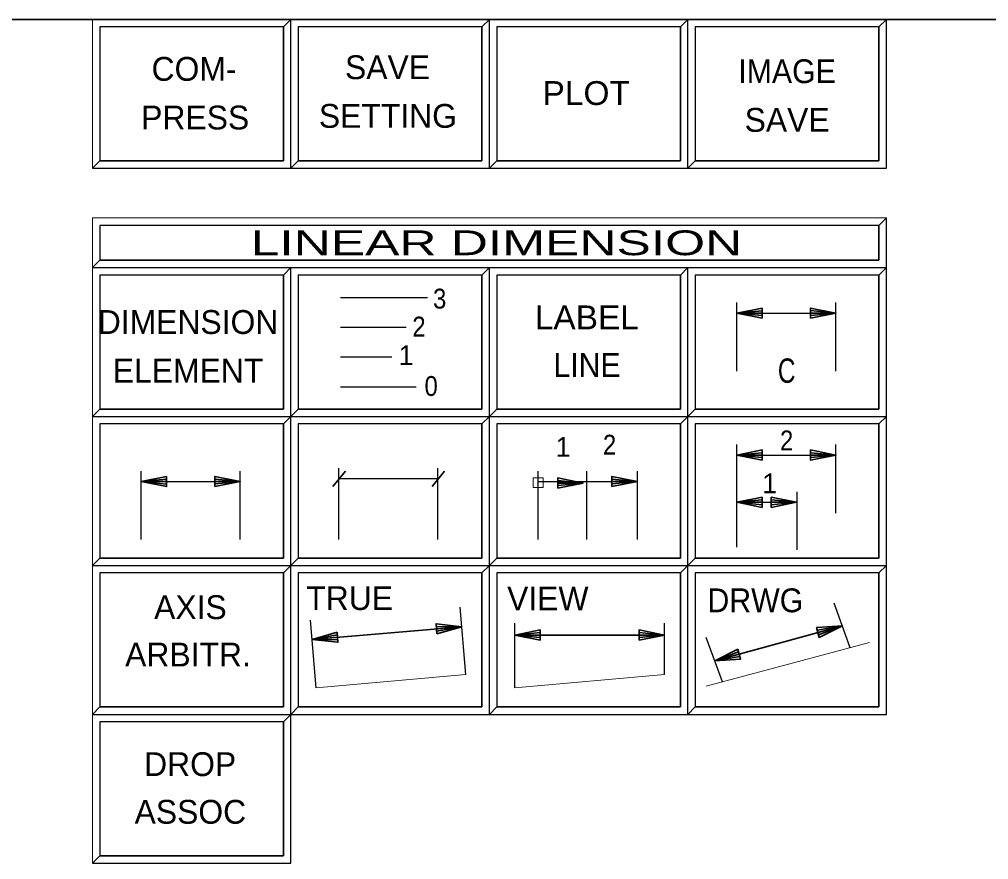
# Model space of a CAD drawing. Extents: x 95906.8 to 95923.6, y 90964.8 to 90972.8.
# Drawn here: x 95908.785 to 95910.738, y 90971.069 to 90972.762 of the extents above; entities that cross this region are included whole.
import ezdxf
from ezdxf.enums import TextEntityAlignment as Align

# ---------------------------------------------------------------- set-up
doc = ezdxf.new("R2010")
doc.units = 0
doc.header["$LTSCALE"] = 0.019
for name, color, linetype, lineweight in [('11', 7, 'Continuous', 25), ('12', 7, 'Continuous', 25), ('17', 7, 'Continuous', 25), ('2', 7, 'Continuous', 13), ('3', 7, 'Continuous', 25), ('6', 7, 'Continuous', 25), ('7', 7, 'Continuous', 35)]:
    doc.layers.add(name, color=color, linetype=linetype, lineweight=lineweight)

msp = doc.modelspace()

# ---------------------------------------------------------------- linework, layer by layer
at = {"layer": '11'}
for points in [[(95908.9473, 90972.4767), (95909.3173, 90972.4767), (95909.3173, 90972.7467), (95908.9473, 90972.7467)], [(95909.3473, 90972.4767), (95909.7173, 90972.4767), (95909.7173, 90972.7467), (95909.3473, 90972.7467)], [(95909.7473, 90972.4767), (95910.1173, 90972.4767), (95910.1173, 90972.7467), (95909.7473, 90972.7467)], [(95908.9473, 90971.9767), (95909.3173, 90971.9767), (95909.3173, 90972.2467), (95908.9473, 90972.2467)], [(95909.3473, 90971.9767), (95909.7173, 90971.9767), (95909.7173, 90972.2467), (95909.3473, 90972.2467)], [(95909.7473, 90971.9767), (95910.1173, 90971.9767), (95910.1173, 90972.2467), (95909.7473, 90972.2467)], [(95910.1473, 90971.9767), (95910.5173, 90971.9767), (95910.5173, 90972.2467), (95910.1473, 90972.2467)], [(95909.3473, 90971.6767), (95909.7173, 90971.6767), (95909.7173, 90971.9467), (95909.3473, 90971.9467)], [(95909.7473, 90971.6767), (95910.1173, 90971.6767), (95910.1173, 90971.9467), (95909.7473, 90971.9467)], [(95910.1473, 90971.6767), (95910.5173, 90971.6767), (95910.5173, 90971.9467), (95910.1473, 90971.9467)], [(95908.9473, 90971.3767), (95909.3173, 90971.3767), (95909.3173, 90971.6467), (95908.9473, 90971.6467)], [(95909.3473, 90971.3767), (95909.7173, 90971.3767), (95909.7173, 90971.6467), (95909.3473, 90971.6467)], [(95909.7473, 90971.3767), (95910.1173, 90971.3767), (95910.1173, 90971.6467), (95909.7473, 90971.6467)], [(95910.1473, 90971.3767), (95910.5173, 90971.3767), (95910.5173, 90971.6467), (95910.1473, 90971.6467)], [(95908.9473, 90971.0767), (95909.3173, 90971.0767), (95909.3173, 90971.3467), (95908.9473, 90971.3467)]]:
    msp.add_lwpolyline(points, close=True, dxfattribs=at)
at = {"layer": '12'}
for points in [[(95910.1473, 90972.4767), (95910.5173, 90972.4767), (95910.5173, 90972.7467), (95910.1473, 90972.7467)], [(95908.9473, 90971.6767), (95909.3173, 90971.6767), (95909.3173, 90971.9467), (95908.9473, 90971.9467)]]:
    msp.add_lwpolyline(points, close=True, dxfattribs=at)
at = {"layer": '17'}
msp.add_lwpolyline([(95908.9473, 90972.2767), (95910.5173, 90972.2767), (95910.5173, 90972.3467), (95908.9473, 90972.3467)], close=True, dxfattribs=at)
at = {"layer": '2'}
for points in [[(95908.9323, 90972.7617), (95908.9323, 90972.4617), (95908.9473, 90972.4767), (95908.9473, 90972.7467), (95909.3173, 90972.7467), (95909.3323, 90972.7617)], [(95909.3323, 90972.7617), (95909.3323, 90972.4617), (95909.3473, 90972.4767), (95909.3473, 90972.7467), (95909.7173, 90972.7467), (95909.7323, 90972.7617)], [(95909.7323, 90972.7617), (95909.7323, 90972.4617), (95909.7473, 90972.4767), (95909.7473, 90972.7467), (95910.1173, 90972.7467), (95910.1323, 90972.7617)], [(95910.1323, 90972.7617), (95910.1323, 90972.4617), (95910.1473, 90972.4767), (95910.1473, 90972.7467), (95910.5173, 90972.7467), (95910.5323, 90972.7617)], [(95908.9323, 90972.3617), (95908.9323, 90972.2617), (95908.9473, 90972.2767), (95908.9473, 90972.3467), (95910.5173, 90972.3467), (95910.5323, 90972.3617)], [(95908.9323, 90972.2617), (95908.9323, 90971.9617), (95908.9473, 90971.9767), (95908.9473, 90972.2467), (95909.3173, 90972.2467), (95909.3323, 90972.2617)], [(95909.3323, 90972.2617), (95909.3323, 90971.9617), (95909.3473, 90971.9767), (95909.3473, 90972.2467), (95909.7173, 90972.2467), (95909.7323, 90972.2617)], [(95909.7323, 90972.2617), (95909.7323, 90971.9617), (95909.7473, 90971.9767), (95909.7473, 90972.2467), (95910.1173, 90972.2467), (95910.1323, 90972.2617)], [(95910.1323, 90972.2617), (95910.1323, 90971.9617), (95910.1473, 90971.9767), (95910.1473, 90972.2467), (95910.5173, 90972.2467), (95910.5323, 90972.2617)], [(95908.9323, 90971.9617), (95908.9323, 90971.6617), (95908.9473, 90971.6767), (95908.9473, 90971.9467), (95909.3173, 90971.9467), (95909.3323, 90971.9617)], [(95909.3323, 90971.9617), (95909.3323, 90971.6617), (95909.3473, 90971.6767), (95909.3473, 90971.9467), (95909.7173, 90971.9467), (95909.7323, 90971.9617)], [(95909.7323, 90971.9617), (95909.7323, 90971.6617), (95909.7473, 90971.6767), (95909.7473, 90971.9467), (95910.1173, 90971.9467), (95910.1323, 90971.9617)], [(95910.1323, 90971.9617), (95910.1323, 90971.6617), (95910.1473, 90971.6767), (95910.1473, 90971.9467), (95910.5173, 90971.9467), (95910.5323, 90971.9617)], [(95908.9323, 90971.6617), (95908.9323, 90971.3617), (95908.9473, 90971.3767), (95908.9473, 90971.6467), (95909.3173, 90971.6467), (95909.3323, 90971.6617)], [(95909.3323, 90971.6617), (95909.3323, 90971.3617), (95909.3473, 90971.3767), (95909.3473, 90971.6467), (95909.7173, 90971.6467), (95909.7323, 90971.6617)], [(95909.7323, 90971.6617), (95909.7323, 90971.3617), (95909.7473, 90971.3767), (95909.7473, 90971.6467), (95910.1173, 90971.6467), (95910.1323, 90971.6617)], [(95910.1323, 90971.6617), (95910.1323, 90971.3617), (95910.1473, 90971.3767), (95910.1473, 90971.6467), (95910.5173, 90971.6467), (95910.5323, 90971.6617)], [(95908.9323, 90971.3617), (95908.9323, 90971.0617), (95908.9473, 90971.0767), (95908.9473, 90971.3467), (95909.3173, 90971.3467), (95909.3323, 90971.3617)]]:
    msp.add_lwpolyline(points, close=True, dxfattribs=at)
at = {"layer": '3'}
for points in [[(95908.9323, 90972.4617), (95909.3323, 90972.4617), (95909.3323, 90972.7617), (95909.3173, 90972.7467), (95909.3173, 90972.4767), (95908.9473, 90972.4767)], [(95909.3323, 90972.4617), (95909.7323, 90972.4617), (95909.7323, 90972.7617), (95909.7173, 90972.7467), (95909.7173, 90972.4767), (95909.3473, 90972.4767)], [(95909.7323, 90972.4617), (95910.1323, 90972.4617), (95910.1323, 90972.7617), (95910.1173, 90972.7467), (95910.1173, 90972.4767), (95909.7473, 90972.4767)], [(95910.1323, 90972.4617), (95910.5323, 90972.4617), (95910.5323, 90972.7617), (95910.5173, 90972.7467), (95910.5173, 90972.4767), (95910.1473, 90972.4767)], [(95908.9323, 90972.2617), (95910.5323, 90972.2617), (95910.5323, 90972.3617), (95910.5173, 90972.3467), (95910.5173, 90972.2767), (95908.9473, 90972.2767)], [(95908.9323, 90971.9617), (95909.3323, 90971.9617), (95909.3323, 90972.2617), (95909.3173, 90972.2467), (95909.3173, 90971.9767), (95908.9473, 90971.9767)], [(95909.3323, 90971.9617), (95909.7323, 90971.9617), (95909.7323, 90972.2617), (95909.7173, 90972.2467), (95909.7173, 90971.9767), (95909.3473, 90971.9767)], [(95909.7323, 90971.9617), (95910.1323, 90971.9617), (95910.1323, 90972.2617), (95910.1173, 90972.2467), (95910.1173, 90971.9767), (95909.7473, 90971.9767)], [(95910.1323, 90971.9617), (95910.5323, 90971.9617), (95910.5323, 90972.2617), (95910.5173, 90972.2467), (95910.5173, 90971.9767), (95910.1473, 90971.9767)], [(95908.9323, 90971.6617), (95909.3323, 90971.6617), (95909.3323, 90971.9617), (95909.3173, 90971.9467), (95909.3173, 90971.6767), (95908.9473, 90971.6767)], [(95909.3323, 90971.6617), (95909.7323, 90971.6617), (95909.7323, 90971.9617), (95909.7173, 90971.9467), (95909.7173, 90971.6767), (95909.3473, 90971.6767)], [(95909.7323, 90971.6617), (95910.1323, 90971.6617), (95910.1323, 90971.9617), (95910.1173, 90971.9467), (95910.1173, 90971.6767), (95909.7473, 90971.6767)], [(95910.1323, 90971.6617), (95910.5323, 90971.6617), (95910.5323, 90971.9617), (95910.5173, 90971.9467), (95910.5173, 90971.6767), (95910.1473, 90971.6767)], [(95908.9323, 90971.3617), (95909.3323, 90971.3617), (95909.3323, 90971.6617), (95909.3173, 90971.6467), (95909.3173, 90971.3767), (95908.9473, 90971.3767)], [(95909.3323, 90971.3617), (95909.7323, 90971.3617), (95909.7323, 90971.6617), (95909.7173, 90971.6467), (95909.7173, 90971.3767), (95909.3473, 90971.3767)], [(95909.7323, 90971.3617), (95910.1323, 90971.3617), (95910.1323, 90971.6617), (95910.1173, 90971.6467), (95910.1173, 90971.3767), (95909.7473, 90971.3767)], [(95910.1323, 90971.3617), (95910.5323, 90971.3617), (95910.5323, 90971.6617), (95910.5173, 90971.6467), (95910.5173, 90971.3767), (95910.1473, 90971.3767)], [(95908.9323, 90971.0617), (95909.3323, 90971.0617), (95909.3323, 90971.3617), (95909.3173, 90971.3467), (95909.3173, 90971.0767), (95908.9473, 90971.0767)]]:
    msp.add_lwpolyline(points, close=True, dxfattribs=at)
at = {"layer": '6'}
for p, q in [((95909.4323, 90972.2017), (95909.6076, 90972.2017)), ((95910.2307, 90972.0533), (95910.2307, 90972.1912)), ((95910.4305, 90972.0533), (95910.4305, 90972.1912)), ((95910.2307, 90972.1701), (95910.4305, 90972.1701)), ((95909.4323, 90972.1417), (95909.5646, 90972.1417)), ((95909.4323, 90972.0817), (95909.5356, 90972.0817)), ((95909.4323, 90972.0217), (95909.5847, 90972.0217)), ((95910.2307, 90971.6987), (95910.2307, 90971.9052)), ((95910.4305, 90971.7673), (95910.4305, 90971.9052)), ((95910.2307, 90971.8841), (95910.4305, 90971.8841)), ((95909.4289, 90971.714), (95909.4289, 90971.858)), ((95909.6287, 90971.714), (95909.6287, 90971.858)), ((95909.0307, 90971.714), (95909.0307, 90971.8519)), ((95909.2305, 90971.714), (95909.2305, 90971.8519)), ((95909.4289, 90971.8369), (95909.6287, 90971.8369)), ((95909.8307, 90971.714), (95909.8307, 90971.8519)), ((95909.929, 90971.714), (95909.929, 90971.8519)), ((95910.0305, 90971.714), (95910.0305, 90971.8519)), ((95909.0307, 90971.8308), (95909.2305, 90971.8308)), ((95909.8307, 90971.8308), (95910.0305, 90971.8308)), ((95910.3526, 90971.6929), (95910.3526, 90971.81)), ((95910.2307, 90971.7889), (95910.3515, 90971.7889)), ((95910.4596, 90971.4961), (95910.427, 90971.5856)), ((95909.6851, 90971.4419), (95909.6732, 90971.5776)), ((95909.3835, 90971.4155), (95909.3716, 90971.5512)), ((95909.7835, 90971.4155), (95909.7835, 90971.5454)), ((95910.0851, 90971.4419), (95910.0851, 90971.5454)), ((95910.2019, 90971.427), (95910.1693, 90971.5165))]:
    msp.add_line(p, q, dxfattribs=at)
at = {"layer": '6', "lineweight": 35}
for p, q in [((95910.2307, 90972.1701), (95910.2819, 90972.1749)), ((95910.2819, 90972.1701), (95910.2307, 90972.1701)), ((95910.3793, 90972.1701), (95910.4305, 90972.1701)), ((95910.4305, 90972.1701), (95910.3793, 90972.1653)), ((95910.2307, 90971.8841), (95910.2819, 90971.8889)), ((95910.2307, 90971.8841), (95910.2819, 90971.8889)), ((95910.2819, 90971.8841), (95910.2307, 90971.8841)), ((95910.2819, 90971.8841), (95910.2307, 90971.8841)), ((95910.4305, 90971.8841), (95910.3793, 90971.8889)), ((95910.4305, 90971.8841), (95910.3793, 90971.8889)), ((95910.3793, 90971.8841), (95910.4305, 90971.8841)), ((95910.3793, 90971.8841), (95910.4305, 90971.8841)), ((95909.0307, 90971.8308), (95909.0819, 90971.8356)), ((95909.417, 90971.821), (95909.4423, 90971.8518)), ((95909.6169, 90971.821), (95909.6422, 90971.8518)), ((95909.0819, 90971.8308), (95909.0307, 90971.8308)), ((95909.1793, 90971.8308), (95909.2305, 90971.8308)), ((95909.2305, 90971.8308), (95909.1793, 90971.826)), ((95909.87, 90971.8278), (95909.9212, 90971.8278)), ((95909.9212, 90971.8278), (95909.87, 90971.823)), ((95909.9793, 90971.8308), (95910.0305, 90971.8308)), ((95910.0305, 90971.8308), (95909.9793, 90971.826)), ((95910.2307, 90971.7889), (95910.2819, 90971.7937)), ((95910.2819, 90971.7889), (95910.2307, 90971.7889)), ((95910.3003, 90971.7889), (95910.3515, 90971.7889)), ((95910.3515, 90971.7889), (95910.3003, 90971.7841)), ((95909.3751, 90971.5129), (95909.6767, 90971.5384)), ((95909.3751, 90971.5129), (95909.4257, 90971.522)), ((95909.6257, 90971.5341), (95909.6767, 90971.5384)), ((95909.6767, 90971.5384), (95909.6261, 90971.5293)), ((95909.7835, 90971.5216), (95909.8347, 90971.5264)), ((95909.7835, 90971.5216), (95910.0851, 90971.5216)), ((95909.8347, 90971.5216), (95909.7835, 90971.5216)), ((95910.0339, 90971.5216), (95910.0851, 90971.5216)), ((95910.0851, 90971.5216), (95910.0339, 90971.5168)), ((95910.1865, 90971.4695), (95910.4436, 90971.5403)), ((95910.3942, 90971.5267), (95910.4436, 90971.5403)), ((95910.4436, 90971.5403), (95910.3955, 90971.5221)), ((95909.4261, 90971.5172), (95909.3751, 90971.5129)), ((95910.1865, 90971.4695), (95910.2346, 90971.4877)), ((95910.2359, 90971.4831), (95910.1865, 90971.4695))]:
    msp.add_line(p, q, dxfattribs=at)
at = {"layer": '6', "lineweight": 13}
for p, q in [((95910.1695, 90971.4183), (95910.4981, 90971.5064)), ((95909.3835, 90971.4155), (95909.6851, 90971.4419)), ((95909.7835, 90971.4155), (95910.0851, 90971.4419))]:
    msp.add_line(p, q, dxfattribs=at)
at = {"layer": '6', "lineweight": 35}
for points in [[(95910.2819, 90972.1803), (95910.2819, 90972.1599), (95910.2307, 90972.1701)], [(95910.2819, 90972.1803), (95910.2307, 90972.1701), (95910.2819, 90972.1651)], [(95910.3793, 90972.1599), (95910.3793, 90972.1803), (95910.4305, 90972.1701)], [(95910.3793, 90972.1599), (95910.4305, 90972.1701), (95910.3793, 90972.1751)], [(95910.2819, 90971.8943), (95910.2819, 90971.8739), (95910.2307, 90971.8841)], [(95910.2819, 90971.8943), (95910.2307, 90971.8841), (95910.2819, 90971.8791)], [(95910.2819, 90971.8943), (95910.2819, 90971.8739), (95910.2307, 90971.8841)], [(95910.2819, 90971.8943), (95910.2307, 90971.8841), (95910.2819, 90971.8791)], [(95910.3793, 90971.8943), (95910.3793, 90971.8739), (95910.4305, 90971.8841)], [(95910.3793, 90971.8943), (95910.4305, 90971.8841), (95910.3793, 90971.8791)], [(95910.3793, 90971.8943), (95910.3793, 90971.8739), (95910.4305, 90971.8841)], [(95910.3793, 90971.8943), (95910.4305, 90971.8841), (95910.3793, 90971.8791)], [(95909.0819, 90971.841), (95909.0819, 90971.8206), (95909.0307, 90971.8308)], [(95909.0819, 90971.841), (95909.0307, 90971.8308), (95909.0819, 90971.8258)], [(95909.1793, 90971.8206), (95909.1793, 90971.841), (95909.2305, 90971.8308)], [(95909.1793, 90971.8206), (95909.2305, 90971.8308), (95909.1793, 90971.8358)], [(95909.87, 90971.8176), (95909.87, 90971.838), (95909.9212, 90971.8278)], [(95909.9793, 90971.8206), (95909.9793, 90971.841), (95910.0305, 90971.8308)], [(95909.9793, 90971.8206), (95910.0305, 90971.8308), (95909.9793, 90971.8358)], [(95909.87, 90971.8176), (95909.9212, 90971.8278), (95909.87, 90971.8328)], [(95910.2819, 90971.7991), (95910.2819, 90971.7787), (95910.2307, 90971.7889)], [(95910.2819, 90971.7991), (95910.2307, 90971.7889), (95910.2819, 90971.7839)], [(95910.3003, 90971.7787), (95910.3003, 90971.7991), (95910.3515, 90971.7889)], [(95910.3003, 90971.7787), (95910.3515, 90971.7889), (95910.3003, 90971.7939)], [(95909.6265, 90971.5239), (95909.6248, 90971.5443), (95909.6767, 90971.5384)], [(95909.4253, 90971.5274), (95909.427, 90971.507), (95909.3751, 90971.5129)], [(95909.4253, 90971.5274), (95909.3751, 90971.5129), (95909.4265, 90971.5122)], [(95909.6265, 90971.5239), (95909.6767, 90971.5384), (95909.6253, 90971.5391)], [(95909.8347, 90971.5318), (95909.8347, 90971.5114), (95909.7835, 90971.5216)], [(95909.8347, 90971.5318), (95909.7835, 90971.5216), (95909.8347, 90971.5166)], [(95910.0339, 90971.5114), (95910.0339, 90971.5318), (95910.0851, 90971.5216)], [(95910.0339, 90971.5114), (95910.0851, 90971.5216), (95910.0339, 90971.5266)], [(95910.397, 90971.5168), (95910.3915, 90971.5366), (95910.4436, 90971.5403)], [(95910.397, 90971.5168), (95910.4436, 90971.5403), (95910.3929, 90971.5315)], [(95910.2331, 90971.493), (95910.2386, 90971.4732), (95910.1865, 90971.4695)], [(95910.2331, 90971.493), (95910.1865, 90971.4695), (95910.2372, 90971.4783)]]:
    msp.add_lwpolyline(points, dxfattribs=at)
at = {"layer": '6', "lineweight": 13}
msp.add_lwpolyline([(95909.8209, 90971.8185), (95909.8409, 90971.8185), (95909.8409, 90971.8385), (95909.8209, 90971.8385)], close=True, dxfattribs=at)
msp.add_lwpolyline([(95909.8209, 90971.8185), (95909.8409, 90971.8185), (95909.8409, 90971.8385), (95909.8209, 90971.8385)], close=True, dxfattribs=at)
at = {"layer": '7'}
msp.add_lwpolyline([(95906.8323, 90972.7617), (95918.8323, 90972.7617), (95918.8323, 90964.7617), (95906.8323, 90964.7617)], close=True, dxfattribs=at)

# ---------------------------------------------------------------- texts
at = {"layer": '6'}
for s, height, p in [('COM-', 0.048, (95909.1372, 90972.638)), ('SAVE', 0.048, (95909.5271, 90972.6413)), ('PRESS', 0.048, (95909.1396, 90972.54)), ('SETTING', 0.048, (95909.5279, 90972.5433)), ('SAVE', 0.048, (95910.3323, 90972.5353)), ('DIMENSION', 0.048, (95909.1252, 90972.1281)), ('1', 0.04, (95909.5646, 90972.0652)), ('ELEMENT', 0.048, (95909.1252, 90972.0301)), ('1', 0.04, (95909.881, 90971.8806)), ('1', 0.04, (95910.2969, 90971.8071)), ('TRUE', 0.048, (95909.4508, 90971.5719)), ('VIEW', 0.048, (95909.8501, 90971.5711)), ('AXIS', 0.048, (95909.1299, 90971.5537)), ('ARBITR.', 0.048, (95909.125, 90971.4583)), ('DROP', 0.048, (95909.1294, 90971.2375)), ('ASSOC', 0.048, (95909.1298, 90971.1415))]:
    msp.add_text(s, height=height, dxfattribs=at).set_placement(p, align=Align.CENTER)
for s, height, width, p in [('IMAGE', 0.048, 0.95, (95910.3322, 90972.6333)), ('PLOT', 0.048, 1.05, (95909.9275, 90972.5893)), ('3', 0.04, 0.9, (95909.6322, 90972.1792)), ('LABEL', 0.048, 1.05, (95909.9287, 90972.1374)), ('2', 0.04, 0.9, (95909.5905, 90972.1229)), ('LINE', 0.048, 0.95, (95909.9291, 90972.0416)), ('C', 0.0491, 0.75, (95910.3314, 90972.0296)), ('0', 0.04, 0.9, (95909.615, 90972.0032)), ('2', 0.04, 0.9, (95910.3313, 90971.8936)), ('2', 0.04, 0.9, (95909.9745, 90971.885)), ('DRWG', 0.048, 0.95, (95910.2683, 90971.5675))]:
    msp.add_text(s, height=height, dxfattribs=dict(at, width=width)).set_placement(p, align=Align.CENTER)
at = {"layer": '7', "width": 1.55}
msp.add_text('    LINEAR DIMENSION   ', height=0.04999, dxfattribs=at).set_placement((95909.7323, 90972.2867), align=Align.CENTER)

doc.saveas('drawing.dxf')
